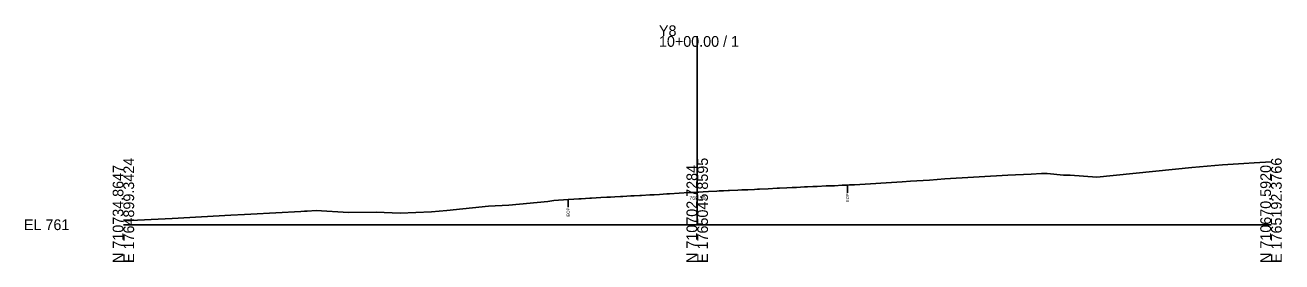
# Model space of a CAD drawing. Extents: x -26 to 1603, y -10 to 1060.
# Drawn here: x -25.7 to 302.8, y -9.7 to 52.1 of the extents above; entities that cross this region are included whole.
import ezdxf

# ---------------------------------------------------------------- set-up
doc = ezdxf.new("R2010")
doc.units = 0
for name, color, linetype in [('Default', 7, 'Continuous'), ('Exist Cross Section Cell', 7, 'Continuous'), ('Exist XS Center Line Elevation Label', 7, 'Continuous'), ('Exist XS Ground Line', 7, 'Continuous'), ('Old_Level_10', 7, 'Continuous')]:
    doc.layers.add(name, color=color, linetype=linetype)

msp = doc.modelspace()

# ---------------------------------------------------------------- linework, layer by layer
at = {"layer": 'Exist Cross Section Cell'}
for p, q in [((150, 0), (150, 49.26)), ((0, 0), (150, 0)), ((150, 0), (300, 0))]:
    msp.add_line(p, q, dxfattribs=at)
at = {"layer": 'Exist XS Ground Line'}
msp.add_lwpolyline([(0, 1.05), (12.74, 1.63), (28.08, 2.5), (31.68, 2.7), (33.27, 2.77), (46.4, 3.48), (47.36, 3.52), (48.03, 3.56), (50.39, 3.69), (58.82, 3.21), (66.08, 3.29), (72.35, 3), (80.53, 3.39), (84.54, 3.74), (95.4, 4.81), (100.77, 5.13), (110.96, 6.08), (112.54, 6.28), (116.26, 6.59), (117.75, 6.69), (119.07, 6.77), (119.69, 6.8), (121.89, 6.92), (122.35, 6.95), (124.81, 7.07), (126.38, 7.16), (127.36, 7.21), (128.48, 7.27), (129.92, 7.35), (130.58, 7.39), (132.68, 7.51), (133.56, 7.56), (135.04, 7.64), (135.46, 7.67), (137.6, 7.77), (138.74, 7.84), (140.16, 7.93), (142.02, 8.04), (142.72, 8.08), (145.29, 8.21), (147.84, 8.37), (148.57, 8.42), (150, 8.5), (150.4, 8.52), (151.57, 8.57), (152.96, 8.66), (155.13, 8.78), (155.77, 8.81), (156.9, 8.86), (158.08, 8.92), (158.41, 8.94), (160.64, 9.03), (161.69, 9.08), (163.2, 9.14), (164.97, 9.23), (165.76, 9.26), (166.26, 9.29), (168.57, 9.4), (170.88, 9.51), (171.52, 9.54), (173.43, 9.64), (174.8, 9.69), (175.99, 9.74), (178.08, 9.85), (178.55, 9.87), (178.86, 9.89), (180.24, 9.95), (181.36, 10), (183.67, 10.11), (184.64, 10.15), (185.91, 10.19), (187.87, 10.29), (189.31, 10.35), (189.84, 10.37), (191.15, 10.44), (203.55, 11.24), (205.73, 11.36), (210.69, 11.67), (214.7, 11.94), (231.2, 12.94), (237.34, 13.18), (240.03, 13.35), (241.48, 13.37), (245.79, 12.96), (247.49, 12.95), (254.46, 12.45), (279.34, 14.98), (287.36, 15.66), (292.94, 15.99), (295.57, 16.15), (300, 16.42)], dxfattribs=at)
at = {"layer": 'Old_Level_10'}
for p, q in [((189.31, 10.35), (189.31, 8.3)), ((116.26, 6.59), (116.26, 4.54))]:
    msp.add_line(p, q, dxfattribs=at)

# ---------------------------------------------------------------- texts
at = {"layer": 'Default'}
msp.add_text('-', height=0.0001, dxfattribs=at).set_placement((0, 0))
at = {"layer": 'Exist Cross Section Cell'}
for s, p in [('Y8', (140, 49.26)), ('10+00.00 / 1', (140, 46.46)), ('EL 761', (-26, -1.4))]:
    msp.add_text(s, height=2.8, dxfattribs=at).set_placement(p)
for s, p in [('E 1764899.3424', (2.8, -10)), ('E 1765045.8595', (152.8, -10)), ('E 1765192.3766', (302.8, -10)), ('N 710734.8647', (0, -10)), ('N 710702.7284', (150, -10)), ('N 710670.5920', (300, -10))]:
    msp.add_text(s, height=2.8, rotation=90, dxfattribs=at).set_placement(p)
at = {"layer": 'Exist XS Center Line Elevation Label'}
msp.add_text('769.50', height=1, dxfattribs=at).set_placement((147.95, 6.5))
at = {"layer": 'Old_Level_10'}
for p in [(189.7, 5.9), (116.65, 2.14)]:
    msp.add_text('EOP', height=0.787, rotation=90, dxfattribs=at).set_placement(p)

doc.saveas('drawing.dxf')
